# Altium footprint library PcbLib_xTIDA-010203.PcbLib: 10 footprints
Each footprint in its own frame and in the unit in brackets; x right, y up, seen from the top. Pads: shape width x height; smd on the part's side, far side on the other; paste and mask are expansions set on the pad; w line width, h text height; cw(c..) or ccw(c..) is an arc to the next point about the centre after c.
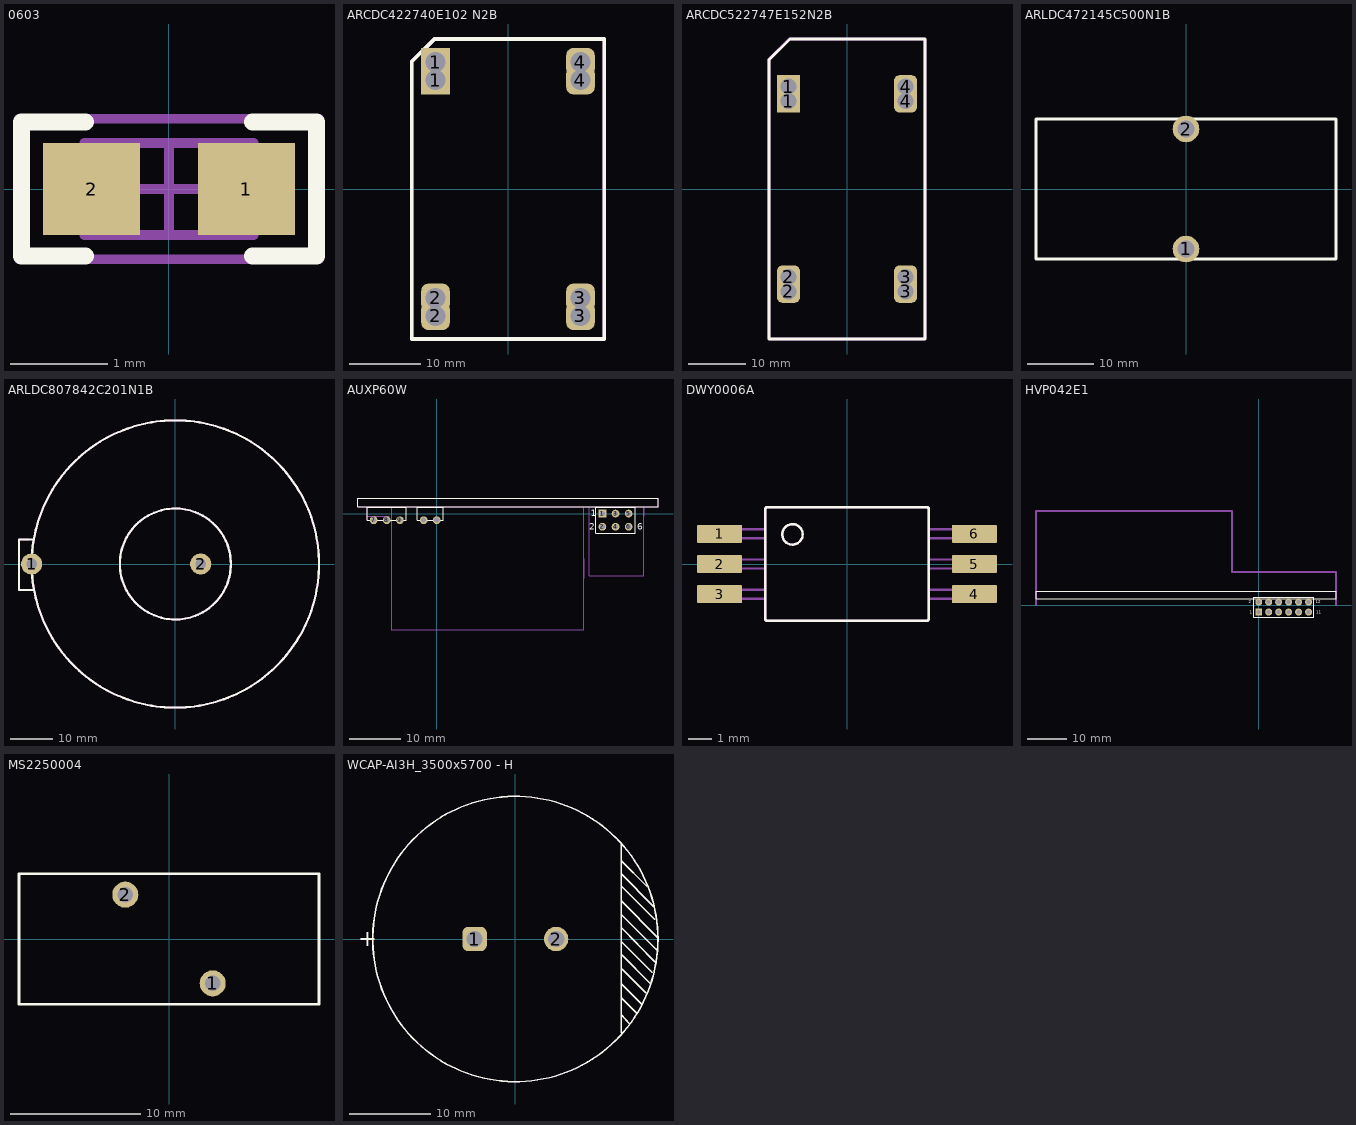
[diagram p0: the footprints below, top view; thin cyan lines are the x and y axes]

## 0603 [mm] "0603 from SM-752 data"
height 1
pads (2):
  rect 1x0.95 smd: 1(0.8,0) 2(-0.8,0)
Top Overlay:
  lines w0.178: -0.864,-0.693 -1.524,-0.693 -1.524,0.691 -0.864,0.691 ; 0.864,-0.693 1.524,-0.693 1.524,0.691 0.864,0.691
M5 Assembly Top:
  lines w0.1: -1.55,-0.725 1.55,-0.725 1.55,0.725 -1.55,0.725 -1.55,-0.725
  text ".Designator" at 1.397,0.381 h0.76
M13 Component Bodies Top:
  lines w0.1: -0.55,-0.475 -0.55,0.475 ; 0.55,-0.475 0.55,0.475 ; -0.875,-0.475 0.875,-0.475 0.875,0.475 -0.875,0.475 -0.875,-0.475
M15 Courtyards Top:
  lines w0.1: -0.475,0 0.475,0 ; 0,-0.475 0,0.475 ; -1.55,-0.725 -1.55,0.725 1.55,0.725 1.55,-0.725 -1.55,-0.725
3D body: height 1, standoff 0, extent -0.874,-0.474 -0.551,0.474
3D body: height 1, standoff 0, extent -0.549,-0.474 0.549,0.474
3D body: height 1, standoff 0, extent 0.551,-0.474 0.874,0.474

## ARCDC422740E102 N2B [mm] "CM CHOKE 1mH, D2.2mm, 7Ts"
height 40
pads (8):
  rect 4x4 hole 2.8: 1(-10.15,15.25) 1(-10.15,17.75)
  rrect50% 4x4 hole 2.8: 2(-10.15,-17.75) 2(-10.15,-15.25) 3(10.15,-17.75) 3(10.15,-15.25) 4(10.15,15.25) 4(10.15,17.75)
Top Overlay:
  lines w0.5: -13.5,17.6 -13.5,-21 13.5,-21 13.5,21 -10.3,21 -13.5,17.8
M5 Assembly Top:
  lines w0.5: -13.5,17.6 -13.5,-21 13.5,-21 13.5,21 -10.3,21 -13.5,17.8
  text ".Designator" at -2.05,-0.45 h1.02
3D body "Wurth_WE-CMB_M.stp": height 26.52, standoff -2.98, extent -8.55,-10.45 8.45,9.55

## ARCDC522747E152N2B [mm] "CM CHOKE 1.6mH, D2.2mm, 8Ts"
height 40
pads (8):
  rect 4x4 hole 2.8: 1(-10.15,15.25) 1(-10.15,17.75)
  rrect50% 4x4 hole 2.8: 2(-10.15,-17.75) 2(-10.15,-15.25) 3(10.15,-17.75) 3(10.15,-15.25) 4(10.15,15.25) 4(10.15,17.75)
Top Overlay:
  lines w0.5: -13.5,-26 -13.5,22.4 -9.9,26 13.5,26 13.5,-26 -13.5,-26
M5 Assembly Top:
  lines w0.5: -13.5,-26 13.5,-26 13.5,26 -10,26 -13.5,22.5 -13.5,-26
  text ".Designator" at -2.05,-0.45 h1.02
3D body "Wurth_WE-CMB_M.stp": height 26.52, standoff -2.98, extent -8.55,-10.45 8.45,9.55

## ARLDC472145C500N1B [mm] "DM CHOKE, 50uH, 9mohm"
height 47
pads (2):
  round 4 hole 2.5: 1(0,-9) 2(0,9)
Top Overlay:
  lines w0.5: -22.5,-10.5 -22.5,10.5 22.5,10.5 22.5,-10.5 -22.5,-10.5

## ARLDC807842C201N1B [mm]
height 35
pads (2):
  round 5 hole 2.5: 1(-34,0) 2(6,0)
Top Overlay:
  circle w0.5: c0,0 r34
  circle w0.5: c0,0 r13.138
  lines w0.5: -33.782,5.842 -36.998,5.842 -36.998,-6.158 -33.528,-6.158
M5 Assembly Top:
  circle w0.5: c0,0 r13.138
  circle w0.5: c0,0 r34
  lines w0.5: -34.798,5.842 -36.998,5.842 -36.998,-6.158 -34.598,-6.158
  text ".Designator" at -4.65,4.75 h1.02

## AUXP60W [mm]
pads (11):
  rect 1.5x1.5 hole 1: 1(32.029,0)
  round 1.5 hole 1: 2(32.029,-2.54) 3(34.569,0) 4(34.569,-2.54) 5(37.109,0) 6(37.109,-2.54) 7(-12.217,-1.27) 8(-9.677,-1.27) 9(-7.137,-1.27) 10(-2.54,-1.27) 11(0,-1.27)
Top Overlay:
  lines w0.2: 33.511,1.27 38.379,1.27 ; 38.379,1.27 38.379,-3.81 30.759,-3.81 30.759,1.27 38.379,1.27 ; -15.24,1.3 -15.24,3 42.788,3 42.788,1.3 -15.24,1.3 ; -13.487,-1.27 -13.487,1.27 -5.867,1.27 -5.867,-1.27 -13.487,-1.27 ; -3.81,-1.27 1.27,-1.27 1.27,1.27 -3.81,1.27 -3.81,-1.27
  text "2" at 29.5,-3.1 h1.27
  text "6" at 38.8,-3.1 h1.27
  text "1" at 29.8,-0.5 h1.27
M5 Assembly Top:
  lines w0.2: -13.487,-1.27 -13.487,1.27 -5.867,1.27 ; -13.487,-0.508 -9.2,-0.538 ; -8.838,1.27 -8.835,-22.503 -3.835,-22.5 28.397,-22.5 28.397,1.27 ; -3.81,1.27 1.27,1.27 ; 28.397,-8.7 28.4,-12.5 ; 28.397,-3 28.397,1.297 ; 28.4,-8 28.4,-4.3 ; 29.5,1.27 29.5,-12 40,-12 40,1.27 ; 30.759,1.27 38.379,1.27 33.511,1.27 ; 40,1.3 40.003,-0.5 ; -15.24,1.3 42.788,1.3 42.788,3 -15.24,3 -15.24,1.3
  text ".Designator" at 6,-0.6 h1.02

## DWY0006A [mm] "SOIC-6"
height 3.43
pads (6):
  rrect13% 1.905x0.76 smd: 1(-5.375,1.27) 2(-5.375,0) 3(-5.375,-1.27) 4(5.375,-1.27) 5(5.375,0) 6(5.375,1.27)
Top Overlay:
  drawing of 461 lines, arcs and shapes, not listed
M5 Assembly Top:
  drawing of 479 lines, arcs and shapes, not listed
  text ".Designator" at -1.8,-0.514 h1.02
3D body "SO-6_8MM.stp": height 3.31, standoff 0, extent -5.75,-2.4 5.75,2.4

## HVP042E1 [mil] "LMG3425R030 Daughter Card"
pads (12):
  rrect10% 70x70 hole 40.16: 1(0,-70)
  round 70 hole 40.16: 2(0,30) 3(100,-70) 4(100,30) 5(200,-70) 6(200,30) 7(300,-70) 8(300,30) 9(400,-70) 10(400,30) 11(500,-70) 12(500,30)
Top Overlay:
  lines w7.87: -2236.22,62.99 775.59,62.99 775.59,137.8 -2236.22,137.8 -2236.22,62.99 ; -50,-120 -50,80 550,80 550,-120 -50,-120
  text "12" at 574.8,16.61 h30
  text "11" at 578.74,-85.75 h30
  text "2" at -98.43,16.61 h30
  text "1" at -90.55,-85.75 h30
M5 Assembly Top:
  lines w3.94: -19.68,-70 19.69,-70 ; 0,-89.68 0,-50.31
  lines w5: -50,-120 550,-120 550,80 -50,80 -50,-120
  lines w19.68: -2236.22,0 -2236.22,944.88 -267.72,944.88 -267.72,330.71 775.59,330.71 775.59,0
  text ".Designator" at -519.68,-155.12 h40

## MS2250004 [mm] "INRSH CURR LIMITER 50 OHM 25% 4A 23MM"
height 32.2
pads (2):
  round 2 hole 1.2: 1(3.35,-3.4) 2(-3.35,3.4)
Top Overlay:
  lines w0.203: -11.5,-5 -11.5,5 11.5,5 11.5,-5 -11.5,-5
M5 Assembly Top:
  lines w0.102: -11.5,-5 11.5,-5 ; -11.5,-5 11.5,-5 ; -11.5,-5 -11.5,5 ; -11.5,-5 -11.5,5 ; -11.5,5 11.5,5 ; -11.5,5 11.5,5 ; 11.5,-5 11.5,5 ; 11.5,-5 11.5,5
  text ".Designator" at -1.65,-0.525 h1.02
M13 Component Bodies Top:
  circle w0.254: c3.35,-3.4 r0.41
  circle w0.254: c-3.35,3.4 r0.41
3D body: height 27.3, standoff 3.69, extent -11.811,-2.794 11.811,2.794
3D body: height 4, standoff 0, extent 2.941,-3.809 3.759,-2.991
3D body: height 4, standoff 0, extent -3.759,2.991 -2.941,3.809

## WCAP-AI3H_3500x5700 - H [mm]
pads (2):
  rrect50% 3x3 hole 2: 1(-5,0)
  round 3 hole 2: 2(5,0)
Top Overlay:
  circle w0.2: c0,0 r17.5
  lines w0.2: 13,-11.5 13,11.6 ; 13,-9.3 14,-10.4 ; 13,-7.2 14.9,-9.1 ; 13,-5.5 15.5,-8 ; 13,-0.3 16.8,-4.1 ; 13,1.4 17.1,-2.8 ; 13,3 17.4,-1.4 ; 13,4.7 17.4,0.2 ; 13,6.5 17.1,2.4 ; 13,8 16.9,4 ; 13,9.6 16.1,6.5 ; 13.1,-3.7 16,-6.6 ; 13.1,-2 16.5,-5.4
  text "+" at -19.3,-0.9 h2
M5 Assembly Top:
  circle w0.1: c0,0 r17.5
  text ".Designator" at -1.8,-0.514 h1.02
  text "+" at -19.2,-1 h2
3D body "WCAP-AI3H_3500x5700.stp": height 56.82, standoff -6.31, extent -17.46,-17.499 17.5,17.5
